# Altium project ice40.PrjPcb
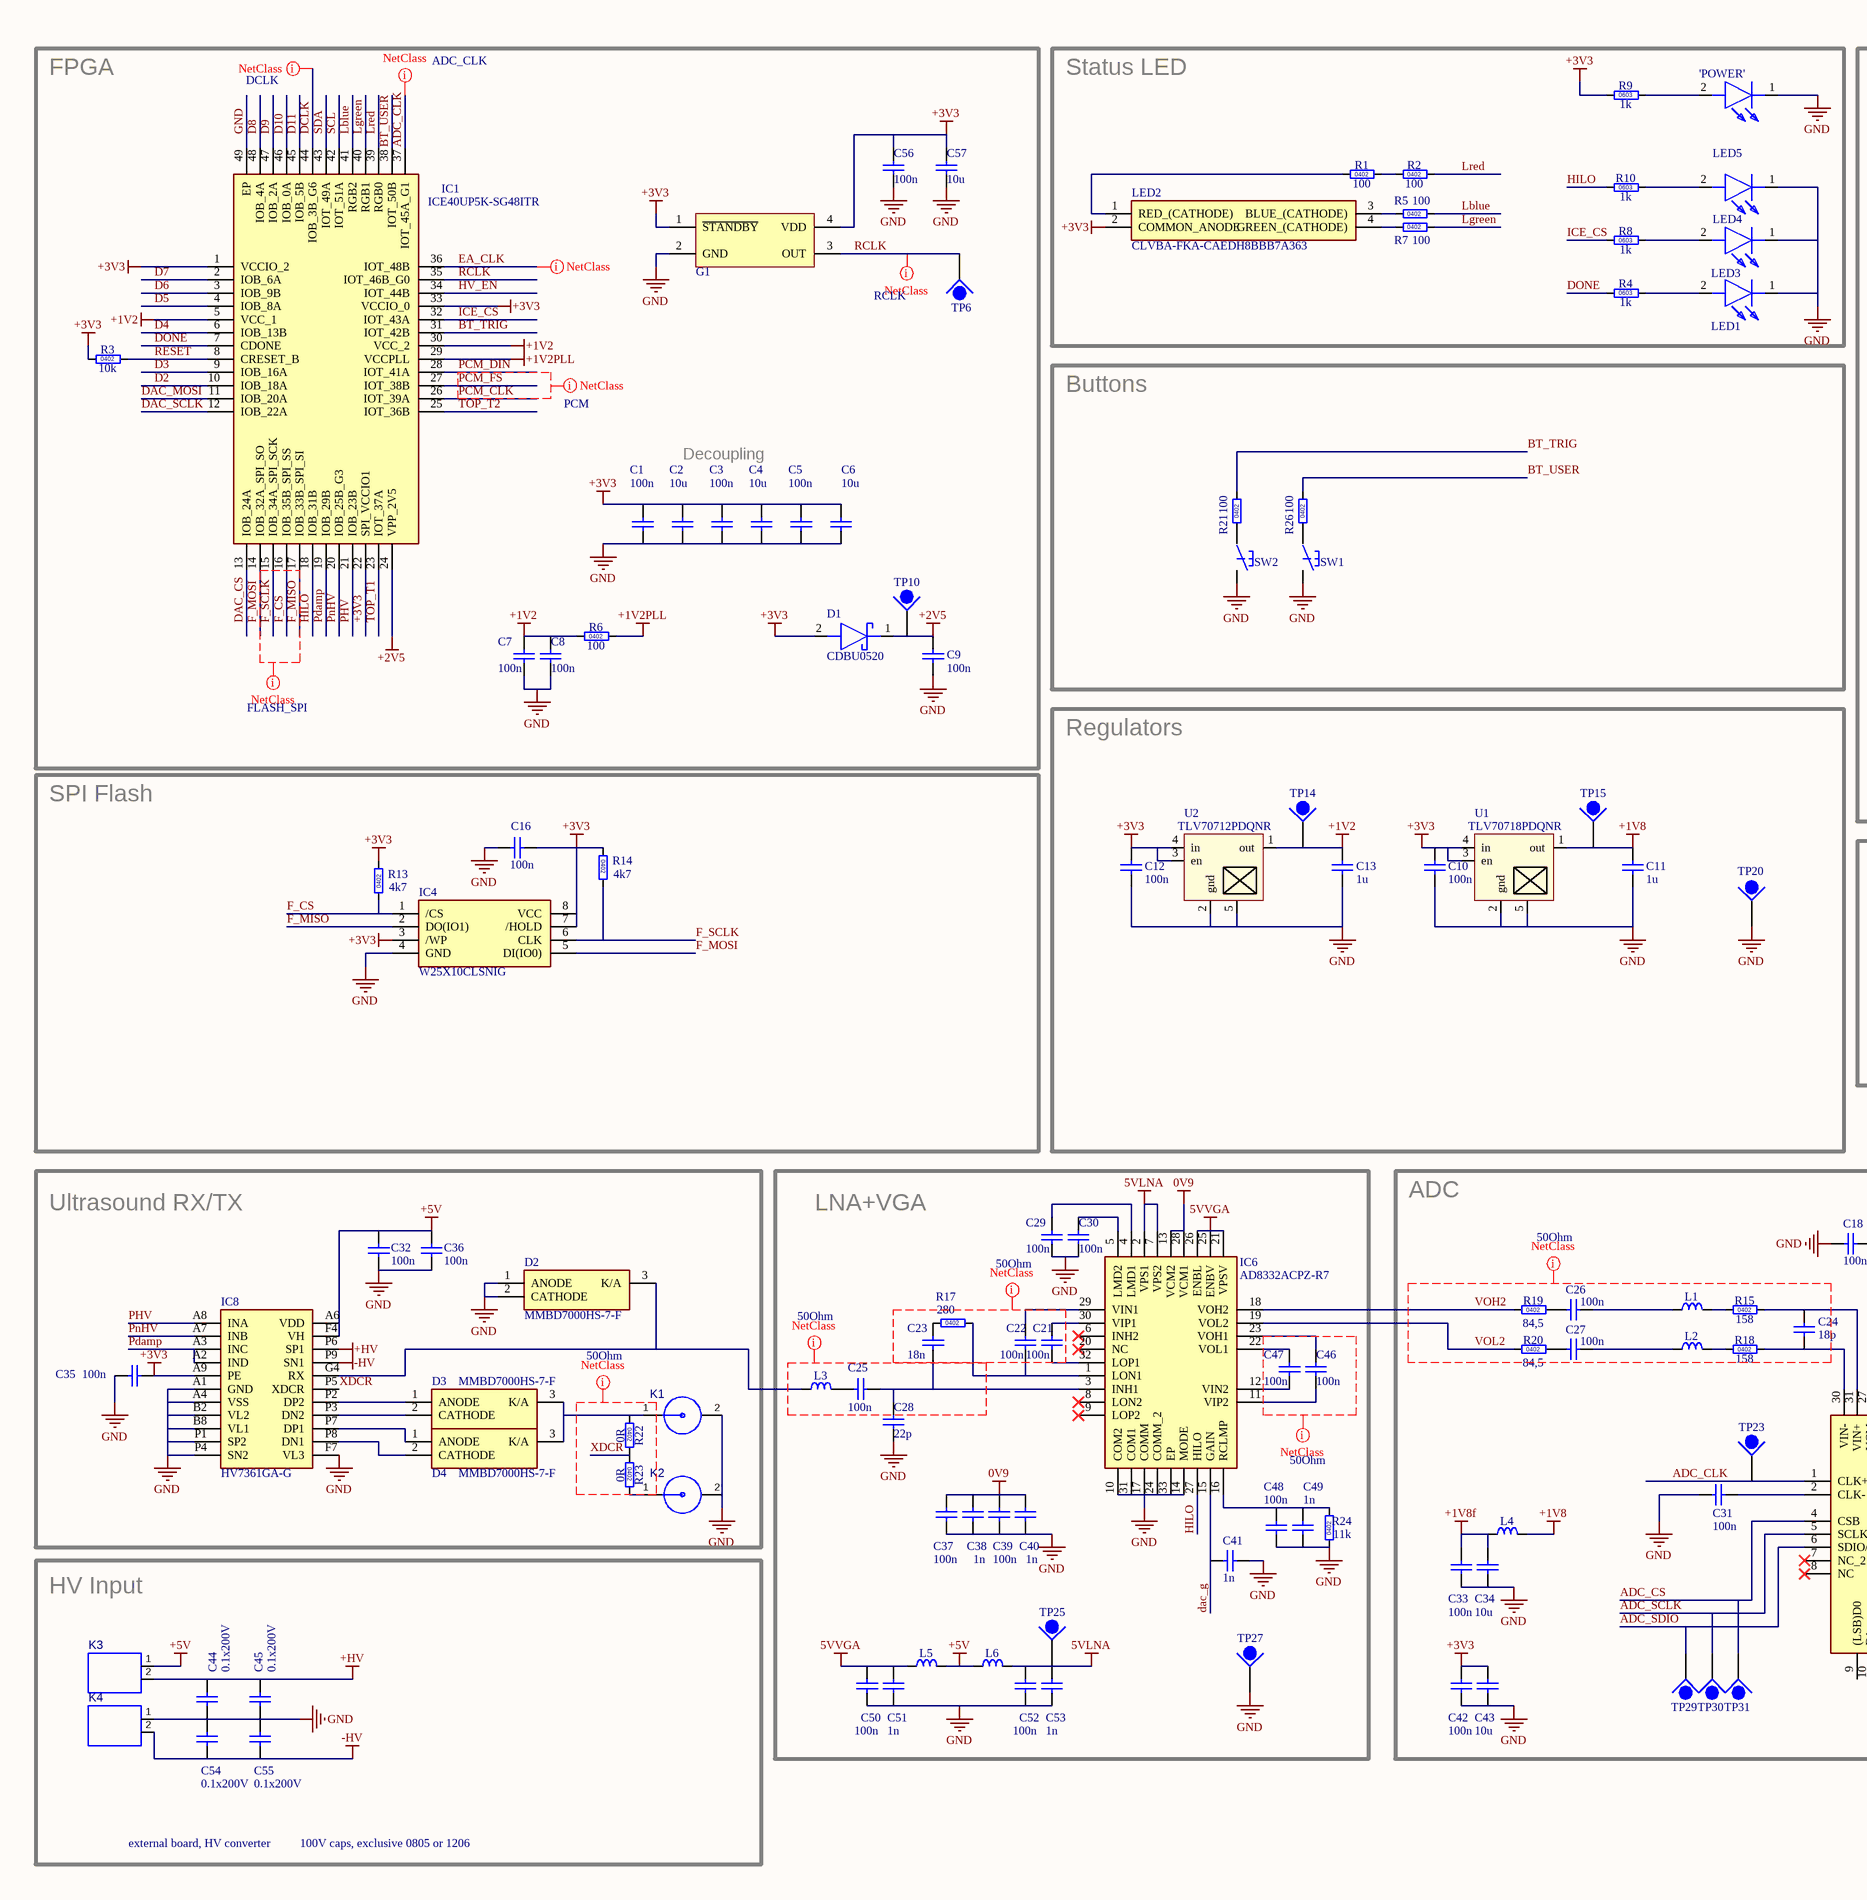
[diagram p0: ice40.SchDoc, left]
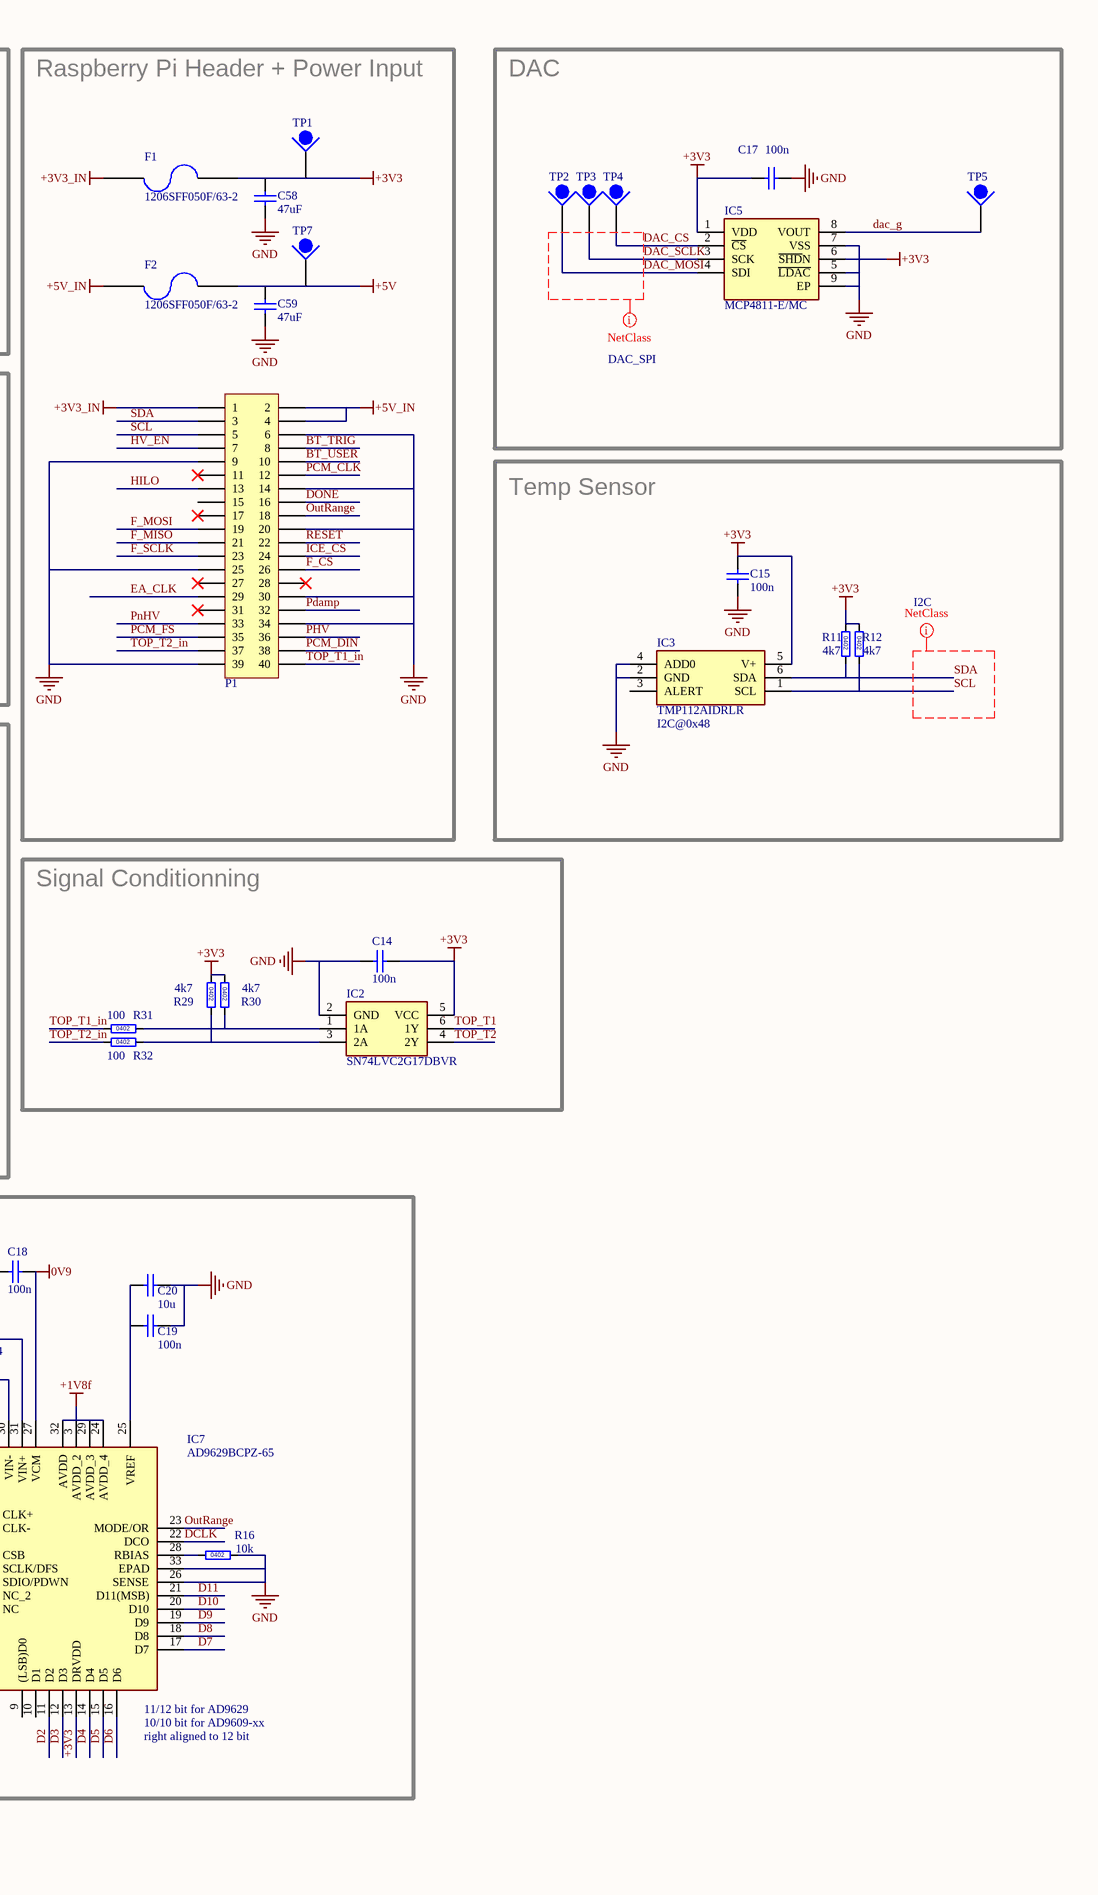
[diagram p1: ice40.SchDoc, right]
1 sheet, 140 parts. Net scope: global (net labels, ports and power ports of the same name join across sheets).
Board file: ice.PcbDoc

## Sheet ice40.SchDoc
size A2; Organization: Altium Limited; Address1: 75 Boul de Mortagne; Address2: Boucherville; Address3: J4B 6Y4; Address4: Canada; ResearchCenter: EME

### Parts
C1  value 100n  [SM0402_3D_cap]  (hidden comment: cap0402)
C2  value 10u  [SM0402_3D_cap]  (hidden comment: cap0402)
C3  value 100n  [SM0402_3D_cap]  (hidden comment: cap0402)
C4  value 10u  [SM0402_3D_cap]  (hidden comment: cap0402)
C5  value 100n  [SM0402_3D_cap]  (hidden comment: cap0402)
C6  value 10u  [SM0402_3D_cap]  (hidden comment: cap0402)
C7  value 100n  [SM0402_3D_cap]  (hidden comment: cap0402)
C8  value 100n  [SM0402_3D_cap]  (hidden comment: cap0402)
C9  value 100n  [SM0402_3D_cap]  (hidden comment: cap0402)
C10  value 100n  [SM0402_3D_cap]  (hidden comment: cap0402)
C11  value 1u  [SM0402_3D_cap]  (hidden comment: cap0402)
C12  value 100n  [SM0402_3D_cap]  (hidden comment: cap0402)
C13  value 1u  [SM0402_3D_cap]  (hidden comment: cap0402)
C14  value 100n  [SM0402_3D_cap]  (hidden comment: cap0402)
C15  value 100n  [SM0402_3D_cap]  (hidden comment: cap0402)
C16  value 100n  [SM0402_3D_cap]  (hidden comment: cap0402)
C17  value 100n  [SM0402_3D_cap]  (hidden comment: cap0402)
C18  value 100n  [SM0402_3D_cap]  (hidden comment: cap0402)
C19  value 100n  [SM0402_3D_cap]  (hidden comment: cap0402)
C20  value 10u  [SM0402_3D_cap]  (hidden comment: cap0402)
C21  value 100n  [SM0402_3D_cap]  (hidden comment: cap0402)
C22  value 100n  [SM0402_3D_cap]  (hidden comment: cap0402)
C23  value 18n  [SM0402_3D_cap]  (hidden comment: cap0402)
C24  value 18p  [SM0402_3D_cap]  (hidden comment: cap0402)
C25  value 100n  [SM0402_3D_cap]  (hidden comment: cap0402)
C26  value 100n  [SM0402_3D_cap]  (hidden comment: cap0402)
C27  value 100n  [SM0402_3D_cap]  (hidden comment: cap0402)
C28  value 22p  [SM0402_3D_cap]  (hidden comment: cap0402)
C29  value 100n  [SM0402_3D_cap]  (hidden comment: cap0402)
C30  value 100n  [SM0402_3D_cap]  (hidden comment: cap0402)
C31  value 100n  [SM0402_3D_cap]  (hidden comment: cap0402)
C32  value 100n  [SM0402_3D_cap]  (hidden comment: cap0402)
C33  value 100n  [SM0402_3D_cap]  (hidden comment: cap0402)
C34  value 10u  [SM0402_3D_cap]  (hidden comment: cap0402)
C35  value 100n  [SM0402_3D_cap]  (hidden comment: cap0402)
C36  value 100n  [SM0402_3D_cap]  (hidden comment: cap0402)
C37  value 100n  [SM0402_3D_cap]  (hidden comment: cap0402)
C38  value 1n  [SM0402_3D_cap]  (hidden comment: cap0402)
C39  value 100n  [SM0402_3D_cap]  (hidden comment: cap0402)
C40  value 1n  [SM0402_3D_cap]  (hidden comment: cap0402)
C41  value 1n  [SM0402_3D_cap]  (hidden comment: cap0402)
C42  value 100n  [SM0402_3D_cap]  (hidden comment: cap0402)
C43  value 10u  [SM0402_3D_cap]  (hidden comment: cap0402)
C44  value 0.1x200V  [SM0805]  (hidden comment: cap0805)
C45  value 0.1x200V  [SM1206]  (hidden comment: cap1206)
C46  value 100n  [SM0402_3D_cap]  (hidden comment: cap0402)
C47  value 100n  [SM0402_3D_cap]  (hidden comment: cap0402)
C48  value 100n  [SM0402_3D_cap]  (hidden comment: cap0402)
C49  value 1n  [SM0402_3D_cap]  (hidden comment: cap0402)
C50  value 100n  [SM0402_3D_cap]  (hidden comment: cap0402)
C51  value 1n  [SM0402_3D_cap]  (hidden comment: cap0402)
C52  value 100n  [SM0402_3D_cap]  (hidden comment: cap0402)
C53  value 1n  [SM0402_3D_cap]  (hidden comment: cap0402)
C54  value 0.1x200V  [SM0805]  (hidden comment: cap0805)
C55  value 0.1x200V  [SM1206]  (hidden comment: cap1206)
C56  value 100n  [SM0402_3D_cap]  (hidden comment: cap0402)
C57  value 10u  [SM0402_3D_cap]  (hidden comment: cap0402)
C58  value 47uF  [CAP_CERAMIC_1206]  (hidden comment: Capacitor)
C59  value 47uF  [CAP_CERAMIC_1206]  (hidden comment: Capacitor)
D1  CDBU0520  [DIOC1709X85N]
D2  MMBD7000HS-7-F  [SOT96P240X110-3N]
D3  MMBD7000HS-7-F  [SOT96P240X110-3N]
D4  MMBD7000HS-7-F  [SOT96P240X110-3N]
F1  1206SFF050F/63-2  [FUSE_1206]
F2  1206SFF050F/63-2  [FUSE_1206]
G1  Oscillator  [OSC_ASEM]  (value not drawn)
IC1  ICE40UP5K-SG48ITR  [QFN50P700X700X100-49N-D]
IC2  SN74LVC2G17DBVR  [SOT95P280X145-6N]
IC3  TMP112AIDRLR  [SOTFL50P160X60-6N]
IC4  W25X10CLSNIG  [SOIC127P600X175-8N]
IC5  MCP4811-E/MC  [SON50P200X300X100-9N]
IC6  AD8332ACPZ-R7  [QFN50P500X500X100-33N]
IC7  AD9629BCPZ-65  [QFN50P500X500X100-33N]
IC8  HV7361GA-G  [BGA22C50P9X14_500X700X105]
K1  SMA_Edge  [AMPHENOL_132357-11]  (value not drawn)
K2  SMA_Edge  [AMPHENOL_132357-11]  (value not drawn)
K3  1x2PLS  [JUMPER2]  (value not drawn)
K4  1x2PLS  [JUMPER2]  (value not drawn)
L1  75R@100MHz  [SM_0805_INDUCTANCE _3D]  (value not drawn)
L2  75R@100MHz  [SM_0805_INDUCTANCE _3D]  (value not drawn)
L3  75R@100MHz  [SM_0805_INDUCTANCE _3D]  (value not drawn)
L4  75R@100MHz  [SM_0805_INDUCTANCE _3D]  (value not drawn)
L5  75R@100MHz  [SM_0805_INDUCTANCE _3D]  (value not drawn)
L6  75R@100MHz  [SM_0805_INDUCTANCE _3D]  (value not drawn)
LED1  HSMW-C191  [LEDC1608X70N]  (value not drawn)
LED2  CLVBA-FKA-CAEDH8BBB7A363  [CLVBAFKACAEDH8BBB7A363]
LED3  HSMW-C191  [LEDC1608X70N]  (value not drawn)
LED4  HSMW-C191  [LEDC1608X70N]  (value not drawn)
LED5  HSMW-C191  [LEDC1608X70N]  (value not drawn)
P1  2x20 2.54mm vertical  [PLD-40]  (value not drawn)
R1  100  [SM0402_3D_res]
R2  100  [SM0402_3D_res]
R3  10k  [SM0402_3D_res]
R4  1k  [SM0603_3D_res]
R5  100  [SM0402_3D_res]
R6  100  [SM0402_3D_res]
R7  100  [SM0402_3D_res]
R8  1k  [SM0603_3D_res]
R9  1k  [SM0603_3D_res]
R10  1k  [SM0603_3D_res]
R11  4k7  [SM0402_3D_res]
R12  4k7  [SM0402_3D_res]
R13  4k7  [SM0402_3D_res]
R14  4k7  [SM0402_3D_res]
R15  158  [SM0402_3D_res]
R16  10k  [SM0402_3D_res]
R17  280  [SM0402_3D_res]
R18  158  [SM0402_3D_res]
R19  84,5  [SM0402_3D_res]
R20  84,5  [SM0402_3D_res]
R21  100  [SM0402_3D_res]
R22  0R  [SM0402_3D_res]
R23  0R  [SM0402_3D_res]
R24  11k  [SM0402_3D_res]
R26  100  [SM0402_3D_res]
R29  4k7  [SM0402_3D_res]
R30  4k7  [SM0402_3D_res]
R31  100  [SM0402_3D_res]
R32  100  [SM0402_3D_res]
SW1  EVQ-P9P02M  [Button 4.7x3.5 _SMT]  (value not drawn)
SW2  EVQ-P9P02M  [Button 4.7x3.5 _SMT]  (value not drawn)
TP1  TP80  [TP80_no_silk]  (value not drawn)  (no BOM)
TP2  TP80  [TP80_no_silk]  (value not drawn)  (no BOM)
TP3  TP80  [TP80_no_silk]  (value not drawn)  (no BOM)
TP4  TP80  [TP80_no_silk]  (value not drawn)  (no BOM)
TP5  TP80  [TP80_no_silk]  (value not drawn)  (no BOM)
TP6  TP80  [TP80_no_silk]  (value not drawn)  (no BOM)
TP7  TP80  [TP80_no_silk]  (value not drawn)  (no BOM)
TP10  TP80  [TP80_no_silk]  (value not drawn)  (no BOM)
TP14  TP80  [TP80_no_silk]  (value not drawn)  (no BOM)
TP15  TP80  [TP80_no_silk]  (value not drawn)  (no BOM)
TP20  TP125X75  [TP125X75]  (value not drawn)  (no BOM)
TP23  TP80  [TP80_no_silk]  (value not drawn)  (no BOM)
TP25  TP80  [TP80_no_silk]  (value not drawn)  (no BOM)
TP27  TP80  [TP80_no_silk]  (value not drawn)  (no BOM)
TP29  TP80  [TP80_no_silk]  (value not drawn)  (no BOM)
TP30  TP80  [TP80_no_silk]  (value not drawn)  (no BOM)
TP31  TP80  [TP80_no_silk]  (value not drawn)  (no BOM)
U1  TLV70718PDQNR  [X2SON - 2]
U2  TLV70712PDQNR  [X2SON - 2]

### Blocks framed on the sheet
FPGA: C1-C9 C56 C57 D1 G1 IC1 R3 R6 TP6 TP10
Status LED: LED1-LED5 R1 R2 R4 R5 R7-R10
Raspberry Pi Header + Power Input: C58 C59 F1 F2 P1 TP1 TP7
DAC: C17 IC5 TP2-TP5
Buttons: R21 R26 SW1 SW2
Temp Sensor: C15 IC3 R11 R12
Regulators: C10-C13 TP14 TP15 TP20 U1 U2
SPI Flash: C16 IC4 R13 R14
Signal Conditionning: C14 IC2 R29-R32
Ultrasound RX/TX: C32 C35 C36 D2-D4 IC8 K1 K2 R22 R23
LNA+VGA: C21-C23 C25 C28-C30 C37-C41 C46-C53 IC6 L3 L5 L6 R17 R24 TP25 TP27
ADC: C18-C20 C24 C26 C27 C31 C33 C34 C42 C43 IC7 L1 L2 L4 R15 R16 R18-R20 TP23 TP29-TP31
HV Input: C44 C45 C54 C55 K3 K4

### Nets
0V9: C18.1 C37.2 C38.2 C39.2 C40.2 IC6.13(VCM2) IC6.28(VCM1) IC7.27(VCM)
5VLNA: C52.2 C53.2 IC6.2(VPS1) IC6.7(VPS2) L6.2 TP25.1
5VVGA: C50.2 C51.2 IC6.21(VPSV) IC6.25(ENBV) IC6.26(ENBL) L5.1
+1V2: C7.2 C8.2 C13.2 IC1.5(VCC_1) IC1.30(VCC_2) R6.1 TP14.1 U2.1(out)
+1V2PLL: IC1.29(VCCPLL) R6.2
+1V8: C11.2 L4.2 TP15.1 U1.1(out)
+1V8f: C33.2 C34.2 IC7.3(AVDD_2) IC7.24(AVDD_4) IC7.29(AVDD_3) IC7.32(AVDD) L4.1
+2V5: C9.2 D1.1(K) IC1.24(VPP_2V5) TP10.1
+3V3: C1.2 C2.2 C3.2 C4.2 C5.2 C6.2 C10.2 C12.2 C14.2 C15.1 C16.1 C17.2 C35.1 C42.2 C43.2 C56.2 C57.2 C58.2 D1.2(A) F1.2 G1.1(~{STANDBY}) G1.4(VDD) IC1.1(VCCIO_2) IC1.22(SPI_VCCIO1) IC1.33(VCCIO_0) IC2.5(VCC) IC3.5(V+) IC4.3(/WP) IC4.7(/HOLD) IC4.8(VCC) IC5.1(VDD) IC5.6(~{SHD}N) IC7.13(DRVDD) IC8.A9(PE) LED2.2(COMMON_ANODE) R3.1 R9.1 R11.1 R12.1 R13.2 R14.1 R29.1 R30.1 TP1.1 U1.3(en) U1.4(in) U2.3(en) U2.4(in)
+3V3_IN: F1.1 P1.1
+5V: C32.1 C36.2 C59.2 F2.2 IC8.A6(VDD) IC8.F4(VH) K3.1 L5.2 L6.1 TP7.1
+5V_IN: F2.1 P1.2 P1.4
+HV: C44.2 C45.2 IC8.P6(SP1) K3.2
-HV: C54.1 C55.1 IC8.P9(SN1) K4.2
GND: C1.1 C2.1 C3.1 C4.1 C5.1 C6.1 C7.1 C8.1 C9.1 C10.1 C11.1 C12.1 C13.1 C14.1 C15.2 C16.2 C17.1 C18.2 C19.1 C20.1 C28.2 C29.2 C30.2 C31.2 C32.2 C33.1 C34.1 C35.2 C36.1 C37.1 C38.1 C39.1 C40.1 C41.1 C42.1 C43.1 C44.1 C45.1 C48.1 C49.1 C50.1 C51.1 C52.1 C53.1 C54.2 C55.2 C56.1 C57.1 C58.1 C59.1 D2.1(ANODE) D2.2(CATHODE) G1.2(GND) IC1.49(EP) IC2.2(GND) IC3.2(GND) IC3.4(ADD0) IC4.4(GND) IC5.5(~{LDAC}) IC5.7(VSS) IC5.9(EP) IC6.10(COM2) IC6.14(MODE) IC6.17(COMM) IC6.24(COMM_2) IC6.31(COM1) IC6.33(EP) IC7.26(SENSE) IC7.33(EPAD) IC8.A1(GND) IC8.A4(VSS) IC8.B2(VL2) IC8.B8(VL1) IC8.F7(VL3) IC8.P1(SP2) IC8.P4(SN2) K1.2 K2.2 K4.1 LED1.1(K) LED3.1(K) LED4.1(K) LED5.1(K) P1.6 P1.9 P1.14 P1.20 P1.25 P1.30 P1.34 P1.39 R16.2 R24.1 SW1.3 SW1.4 SW2.3 SW2.4 TP20.1 TP27.1 U1.2(gnd) U1.5(tp) U2.2(gnd) U2.5(tp)
ADC_CLK: IC1.37(IOT_45A_G1) IC7.1(CLK+) TP23.1
ADC_CS: IC7.4(CSB) TP31.1
ADC_SCLK: IC7.5(SCLK/DFS) TP30.1
ADC_SDIO: IC7.6(SDIO/PDWN) TP29.1
BT_TRIG: IC1.31(IOT_42B) P1.8 R21.2
BT_USER: IC1.38(IOT_50B) P1.10 R26.2
D2: IC1.10(IOB_18A) IC7.11(D2)
D3: IC1.9(IOB_16A) IC7.12(D3)
D4: IC1.6(IOB_13B) IC7.14(D4)
D5: IC1.4(IOB_8A) IC7.15(D5)
D6: IC1.3(IOB_9B) IC7.16(D6)
D7: IC1.2(IOB_6A) IC7.17(D7)
D8: IC1.48(IOB_4A) IC7.18(D8)
D9: IC1.47(IOB_2A) IC7.19(D9)
D10: IC1.46(IOB_0A) IC7.20(D10)
D11: IC1.45(IOB_5B) IC7.21(D11(MSB))
DAC_CS: IC1.13(IOB_24A) IC5.2(~{CS}) TP4.1
dac_g: C41.2 IC5.8(VOUT) IC6.15(GAIN) TP5.1
DAC_MOSI: IC1.11(IOB_20A) IC5.4(SDI) TP2.1
DAC_SCLK: IC1.12(IOB_22A) IC5.3(SCK) TP3.1
DCLK: IC1.44(IOB_3B_G6) IC7.22(DCO)
DONE: IC1.7(CDONE) P1.16 R4.1
EA_CLK: IC1.36(IOT_48B) P1.29
F_CS: IC1.16(IOB_35B_SPI_SS) IC4.1(/CS) P1.26 R13.1
F_MISO: IC1.17(IOB_33B_SPI_SI) IC4.2(DO(IO1)) P1.21
F_MOSI: IC1.14(IOB_32A_SPI_SO) IC4.5(DI(IO0)) P1.19
F_SCLK: IC1.15(IOB_34A_SPI_SCK) IC4.6(CLK) P1.23 R14.2
HILO: IC1.18(IOB_31B) IC6.27(HILO) P1.13 R10.1
HV_EN: IC1.34(IOT_44B) P1.7
ICE_CS: IC1.32(IOT_43A) P1.24 R8.1
Lblue: IC1.41(RGB2) R5.2
Lgreen: IC1.40(RGB1) R7.2
Lred: IC1.39(RGB0) R2.2
OutRange: IC7.23(MODE/OR) P1.18
PCM_CLK: IC1.26(IOT_39A) P1.12
PCM_DIN: IC1.28(IOT_41A) P1.38
PCM_FS: IC1.27(IOT_38B) P1.35
Pdamp: IC1.19(IOB_29B) IC8.A2(IND) IC8.A3(INC) P1.32
PHV: IC1.21(IOB_23B) IC8.A8(INA) P1.36
PnHV: IC1.20(IOB_25B_G3) IC8.A7(INB) P1.33
RCLK: G1.3(OUT) IC1.35(IOT_46B_G0) TP6.1
RESET: IC1.8(CRESET_B) P1.22 R3.2
SCL: IC1.42(IOT_51A) IC3.1(SCL) P1.5 R12.2
SDA: IC1.43(IOT_49A) IC3.6(SDA) P1.3 R11.2
TOP_T1: IC1.23(IOT_37A) IC2.6(1Y)
TOP_T1_in: P1.40 R31.1
TOP_T2: IC1.25(IOT_36B) IC2.4(2Y)
TOP_T2_in: P1.37 R32.1
VOH2: IC6.18(VOH2) R19.1
VOL2: IC6.19(VOL2) R20.1
XDCR: IC8.P5(XDCR) R22.2 R23.1
NetC19_2: C19.2 C20.2 IC7.25(VREF)
NetC21_1: C21.1 IC6.30(VIP1)
NetC21_2: C21.2 IC6.32(LOP1)
NetC22_1: C22.1 IC6.1(LON1) R17.2
NetC22_2: C22.2 IC6.29(VIN1)
NetC23_1: C23.1 C25.1 C28.1 IC6.3(INH1)
NetC23_2: C23.2 R17.1
NetC24_1: C24.1 IC7.30(VIN-) R18.2
NetC24_2: C24.2 IC7.31(VIN+) R15.2
NetC25_2: C25.2 L3.2
NetC26_1: C26.1 L1.1
NetC26_2: C26.2 R19.2
NetC27_1: C27.1 L2.1
NetC27_2: C27.2 R20.2
NetC29_1: C29.1 IC6.4(LMD1)
NetC30_1: C30.1 IC6.5(LMD2)
NetC31_1: C31.1 IC7.2(CLK-)
NetC46_1: C46.1 IC6.11(VIP2)
NetC46_2: C46.2 IC6.23(VOH1)
NetC47_1: C47.1 IC6.12(VIN2)
NetC47_2: C47.2 IC6.22(VOL1)
NetC48_2: C48.2 C49.2 IC6.16(RCLMP) R24.2
NetD2_3: D2.3(K/A) IC8.G4(RX) L3.1
NetD3_1: D3.1(ANODE) IC8.P2(DP2)
NetD3_2: D3.2(CATHODE) IC8.P3(DN2)
NetD3_3: D3.3(K/A) D4.3(K/A) K1.1 R22.1
NetD4_1: D4.1(ANODE) IC8.P7(DP1)
NetD4_2: D4.2(CATHODE) IC8.P8(DN1)
NetIC2_1: IC2.1(1A) R30.2 R31.2
NetIC2_3: IC2.3(2A) R29.2 R32.2
NetIC7_28: IC7.28(RBIAS) R16.1
NetK2_1: K2.1 R23.2
NetL1_2: L1.2 R15.1
NetL2_2: L2.2 R18.1
NetLED1_2: LED1.2(A) R4.2
NetLED2_1: LED2.1(RED_(CATHODE)) R1.1
NetLED2_3: LED2.3(BLUE_(CATHODE)) R5.1
NetLED2_4: LED2.4(GREEN_(CATHODE)) R7.1
NetLED3_2: LED3.2(A) R8.2
NetLED4_2: LED4.2(A) R10.2
NetLED5_2: LED5.2(A) R9.2
NetR1_2: R1.2 R2.1
NetR21_1: R21.1 SW2.1 SW2.2
NetR26_1: R26.1 SW1.1 SW1.2

Not connected (* = marked no-connect by the designer): IC3 3(ALERT); IC6 6(INH2)* 8(LON2)* 9(LOP2)* 20(NC)*; IC7 7(NC_2)* 8(NC)* 9((LSB)D0) 10(D1); P1 11* 15 17* 27* 28* 31*

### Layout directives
net class RCLK: RCLK
net class 50Ohm: (no net found under the mark), VOH2, VOL2, XDCR
net class DCLK: DCLK
net class ADC_CLK: ADC_CLK
net class EA_CLK: EA_CLK
net class FLASH_SPI: F_CS, F_MISO, F_MOSI, F_SCLK
net class PCM: PCM_CLK, PCM_DIN, PCM_FS
net class I2C: SCL, SDA
net class DAC_SPI: DAC_CS, DAC_MOSI, DAC_SCLK

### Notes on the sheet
- (near LED5) 'POWER'
- Decoupling
- (near IC3) I2C@0x48
- (near IC7) 11/12 bit for AD9629
- (near IC7) 10/10 bit for AD9609-xx
- (near IC7) right aligned to 12 bit
- external board, HV converter
- 100V caps, exclusive 0805 or 1206

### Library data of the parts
C1-C43 C46-C53 C56 C57 = cap0402: Capacitor  0402 inch
C44 C54 = cap0805: Capacitor
C45 C55 = cap1206: Capacitor
C58 C59 = C_47uF_1206_SMD_JB_20%_25V_TDK_C: CAP CER 47UF 25V X5R 1206; ManufacturerPartNumber: C3216JB1E476M160AC; Validation Status: Verified; ATT Capacitor Type: Ceramic; ATT Case: 1206 (3216 Metric); ATT Temperature Coefficient: JB; ATT Tolerance: ±20%
D1 = CDBU0520: Schottky Diode; Manufacturer_Name: Comchip Technology
D2-D4 = MMBD7000HS-7-F: Diode; Manufacturer_Name: Diodes Inc.
F1 F2 = 1206SFF050F/63-2: 500mA AC 63V DC Fuse Board Mount Surface Mount 1206; ATT Technology: SMD; ATT Fuse size: 1206
G1 = ASEMB-80.000MHZ-LY-T: OSC MEMS 80 MHZ SMD; Validation Status: Verified; ATT Frequency: 80Mhz; ATT Frequency Stability: ±10ppm; ATT Package / Case: 4-SMD, No Lead (DFN, LCC); ATT Series: ASEMB, Pure Silicon™; ATT Supply Current: 16mA; ATT Supply Voltage: 1.7 V ~ 3.6 V; ATT Type: MEMS (Silicon)
IC1 = ICE40UP5K-SG48ITR: Integrated Circuit; Manufacturer_Name: Lattice Semiconductor
IC2 = SN74LVC2G17DBVR: Integrated Circuit; Manufacturer_Name: Texas Instruments
IC3 = TMP112AIDRLR: Integrated Circuit; Manufacturer_Name: Texas Instruments
IC4 = W25X10CLSNIG: Integrated Circuit; Manufacturer_Name: Winbond
IC5 = MCP4811-E/MC: DAC 1-CH Resistor-String 10-bit Automotive 8-Pin DFN EP Tube; Manufacturer: Microchip; Resolution: 10b; Integral Nonlinearity (INL): 3.5LSB; Output Type: Voltage; Interface: SPI,Serial,3-WIRE; Number of DAC Channels: 1; Nominal Supply Current: 330uA; Max Supply Voltage: 5.5V; Min Supply Voltage: 2.7V; Operating Supply Voltage: 5V; Settling Time: 4.5us; Number of Bits: 10; Polarity: Bipolar; Input Offset Voltage (Vos): 820uV
IC6 = AD8332ACPZ-R7: Integrated Circuit; Manufacturer_Name: Analog Devices
IC7 = AD9629BCPZ-65: Integrated Circuit; Manufacturer_Name: Analog Devices
IC8 = HV7361GA-G: Integrated Circuit; Manufacturer_Name: Microchip
L1 L2 = Ind_Chip_0805: chip inductance; Part Number: IND0805_MURATA_BLM21BB750SN1D; Part Description: SMD EMIFIL Suppression Chip Ferrite Bead; Manufacturer: MURATA; Manufacturer Part Number: AIML-0805HC-1R5M-T; Power: 700mA; Resistance: 0.16R; Tolerance: ±25%; Table: Inductors SMD
L3-L6 = Ind_Chip_0805: Ferrite Beads Multi-Layer 600Ohm 25% 100MHz 1A 0.2Ohm DCR 0603 T/R; Part Number: IND0805_MURATA_BLM21BB750SN1D; Part Description: SMD EMIFIL Suppression Chip Ferrite Bead; Manufacturer: MURATA; Manufacturer Part Number: BLM21BB750SN1D; ManufacturerPartNumber: PBY160808T-601Y-N; Power: 700mA; Resistance: 0.16R; Table: Inductors SMD
LED1 LED3-LED5 = HSMW-C191: LED; Manufacturer_Name: Avago Technologies
LED2 = CLVBA-FKA-CAEDH8BBB7A363: LED; Manufacturer_Name: Cree
P1 = 2x20 2.54mm vertical: Header, 40-Pin
R1-R3 R5-R7 R15-R24 R26 R31 R32 = Res_0402_EU: Part Number: R1206_4K7_1%_0.25W_100PPM; Part Description: General Purpose Thick Film Chip Resistor; Manufacturer: GENERIC; Manufacturer1 Part Number: NRC12F4701TRF; Value: 4k7; Power: 0.25W; TC: ±100ppm/°C; Tolerance: ±1%; Table: Resistors SMD
R4 R8-R10 = Res_0603_EU: Part Number: R1206_4K7_1%_0.25W_100PPM; Part Description: General Purpose Thick Film Chip Resistor; Manufacturer: GENERIC; Manufacturer1 Part Number: NRC12F4701TRF; Value: 4k7; Power: 0.25W; TC: ±100ppm/°C; Tolerance: ±1%; Table: Resistors SMD
R11-R14 R29 R30 = Res_0402_EU: Part Number: R1206_4K7_1%_0.25W_100PPM; Part Description: General Purpose Thick Film Chip Resistor; Manufacturer: GENERIC; Manufacturer1 Part Number: NRC12F4701TRF; Power: 0.25W; TC: ±100ppm/°C; Tolerance: ±1%; Table: Resistors SMD
SW1 SW2 = Button 4.7x3.5 SMT
U1 = TLV70718PDQNR: low drop LDO
U2 = TLV70712PDQNR: low drop LDO

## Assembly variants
HighVoltageCap_0805: not fitted C45 C55 K1 K2 K3 K4 P1
HighVoltageCap_1206: not fitted C44 C54 K1 K2 K3 K4 P1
